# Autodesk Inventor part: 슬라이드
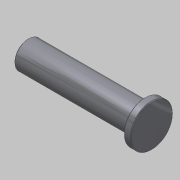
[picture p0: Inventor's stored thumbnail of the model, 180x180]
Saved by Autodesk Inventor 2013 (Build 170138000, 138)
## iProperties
Created: 2013-06
Part Number: 슬라이드
Document SubType Name: Modeling
Designer: SeoGD™[esajin.kr]
Density: 1 g/cm^3
Material: 일반
Mass: 203.978 g
Surface Area: 269.019 cm^2
Volume: 203.978 cm^3
Author: SeoGD™[esajin.kr]
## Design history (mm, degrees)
sketch "스케치1"
  geometry: L1 (-75, 162)-(-75, 58) reference; L2 (-148, 110)-(22, 110); L3 (-148, 110)-(-148, 129); L4 (-148, 129)-(12, 129); L5 (12, 129)-(12, 139); L6 (12, 139)-(22, 139); L7 (22, 139)-(22, 110); 2 further points
  constraints: 12 end point, 3 parallel, 3 perpendicular, 1 midpoint, 1 point on line
  dimensions: "d0" = 58 diameter of L6 L2; "d1" = 38 diameter of L4 L2; "d2" = 10 distance of L5.end L6.end; "d3" = 170 distance of L2.start L2.end; "d4" = 73 distance between parallel lines of L3 L1
revolve "회전1" sketch "스케치1" stored, may be unused: angle "d5" = 90 deg
hole "구멍1" diameter "d11" = 13.376; stored, may be unused: countersink angle "d15" = 90 deg, drill point angle "d17" = 118 deg; dims "d9" = 10, "d10" = 10, "d12" = 22, "d13" = 4, "d14" = 2, "d16" = 25
chamfer "모따기1" distance "d6" = 1; stored, may be unused: second distance "d7" = 2, angle "d8" = 45 deg
node "솔리드1"
node "참조1"
